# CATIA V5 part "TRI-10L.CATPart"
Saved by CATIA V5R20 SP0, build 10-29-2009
Part number: _TRI-10L
Definition: NONE
Nomenclature: _TRI-10L
Source: Unknown
Description: PART-_TRI-10L-DESC
Bounding box of the stored display mesh (mm): x 0 to 17.5, y -5 to 5, z -5 to 5
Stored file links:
  C:\Users\Utente\Desktop\IO LAVORO\3D X SITO CF\X SITO\PLASTICA\TRI\TRI-10L.CATPart
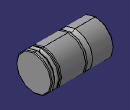
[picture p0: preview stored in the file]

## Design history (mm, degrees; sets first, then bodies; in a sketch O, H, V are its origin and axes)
Body1 "_TRI-10L" (main body)
  Solid1: solid without history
